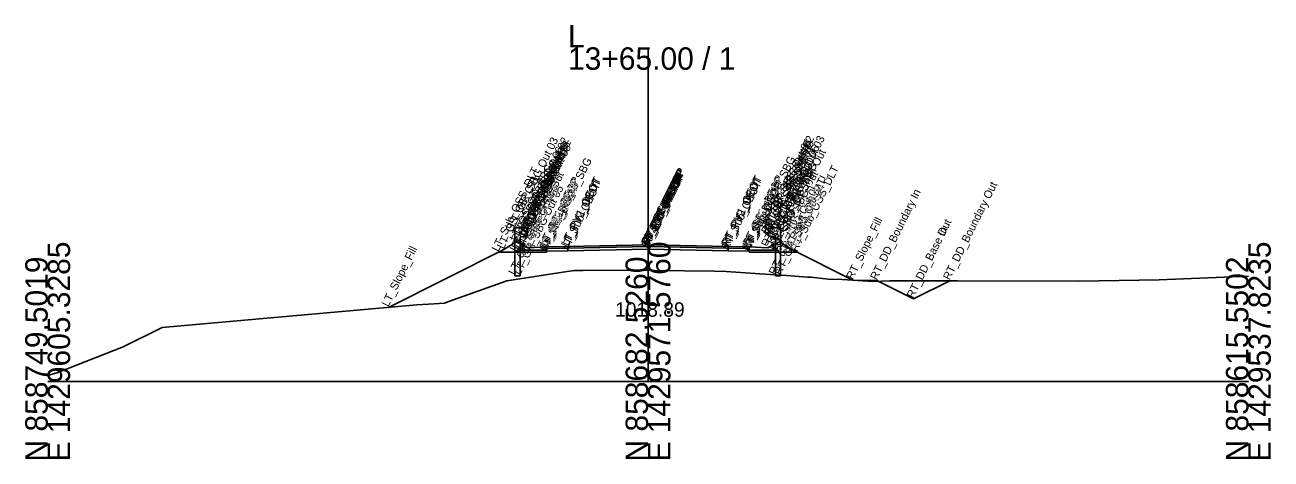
# Model space of a CAD drawing. Extents: x -26 to 2303, y -10 to 19558.
# Drawn here: x 1147.2 to 1302.8, y 11490.3 to 11544.5 of the extents above; entities that cross this region are included whole.
import ezdxf

# ---------------------------------------------------------------- set-up
doc = ezdxf.new("R2010")
doc.units = 0
for name, color, linetype in [('Default', 7, 'Continuous'), ('Exist Cross Section Cell', 7, 'Continuous'), ('Exist XS Center Line Elevation Label', 7, 'Continuous'), ('Exist XS Ground Line', 7, 'Continuous'), ('Prop CMT Conc Surface', 7, 'Continuous'), ('Prop CMT Concrete Structures', 7, 'Continuous'), ('Prop CMT Ditch DDE', 7, 'Continuous'), ('Prop CMT Guardrail SBG', 7, 'Continuous'), ('Prop CMT Pvmt Course 1', 7, 'Continuous'), ('Prop CMT Pvmt Course 2', 7, 'Continuous'), ('Prop CMT Pvmt Course SBG', 7, 'Continuous'), ('Prop CMT Pvmt Surface', 7, 'Continuous'), ('Prop CMT Pvmt Surface Shoulder', 7, 'Continuous'), ('Prop CMT Shld Paved Course 1', 7, 'Continuous'), ('Prop CMT Shld Paved Course 2', 7, 'Continuous'), ('Prop CMT Slope Grass', 7, 'Continuous'), ('Prop CMT Subgrade Earthwork', 7, 'Continuous'), ('Prop XS Dump Level', 7, 'Continuous')]:
    doc.layers.add(name, color=color, linetype=linetype)

msp = doc.modelspace()

# ---------------------------------------------------------------- linework, layer by layer
at = {"layer": 'Exist Cross Section Cell'}
for p, q in [((1225, 11500), (1225, 11541.74)), ((1150, 11500), (1225, 11500)), ((1225, 11500), (1300, 11500))]:
    msp.add_line(p, q, dxfattribs=at)
at = {"layer": 'Exist XS Ground Line'}
msp.add_lwpolyline([(1150, 11500.73), (1151.29, 11501.14), (1159.43, 11504.31), (1164.32, 11506.75), (1196.14, 11509.58), (1198.3, 11509.7), (1199.59, 11509.77), (1200.11, 11510), (1207.36, 11512.57), (1214.92, 11513.73), (1215.81, 11513.85), (1216.88, 11513.86), (1223.94, 11513.91), (1225, 11513.89), (1225.83, 11513.87), (1233.32, 11513.77), (1234.77, 11513.72), (1238.96, 11513.44), (1242.32, 11513.25), (1244.97, 11513.05), (1245.36, 11513.03), (1247.55, 11512.79), (1249.26, 11512.74), (1253.14, 11512.51), (1255.23, 11512.58), (1263.68, 11512.59), (1278.84, 11512.52), (1288.84, 11512.7), (1300, 11513.16)], dxfattribs=at)
at = {"layer": 'Prop CMT Conc Surface'}
for points in [[(1212.3, 11516.81), (1209.97, 11516.71), (1209.3, 11517.06)], [(1237.64, 11516.81), (1239.97, 11516.71), (1240.64, 11517.06)]]:
    msp.add_lwpolyline(points, dxfattribs=at)
at = {"layer": 'Prop CMT Concrete Structures'}
for points in [[(1212.3, 11516.81), (1209.97, 11516.71), (1209.3, 11517.06)], [(1209.3, 11517.06), (1209.3, 11516.39)], [(1209.3, 11516.39), (1212.3, 11516.39)], [(1212.3, 11516.39), (1212.3, 11516.81)], [(1237.64, 11516.81), (1239.97, 11516.71), (1240.64, 11517.06)], [(1237.64, 11516.39), (1237.64, 11516.81)], [(1240.64, 11516.39), (1237.64, 11516.39)], [(1240.64, 11517.06), (1240.64, 11516.39)]]:
    msp.add_lwpolyline(points, dxfattribs=at)
at = {"layer": 'Prop CMT Ditch DDE'}
for points in [[(1250.59, 11512.66), (1253.59, 11512.6), (1258.15, 11510.32)], [(1258.15, 11510.32), (1262.69, 11512.59)], [(1258.15, 11510.32), (1258.15, 11510.32)]]:
    msp.add_lwpolyline(points, dxfattribs=at)
at = {"layer": 'Prop CMT Guardrail SBG'}
for points in [[(1208.37, 11513.21), (1208.37, 11519.21)], [(1208.37, 11519.21), (1209.7, 11519.21), (1209.97, 11518.92)], [(1209.97, 11518.92), (1209.7, 11518.63)], [(1241.57, 11519.21), (1240.24, 11519.21), (1239.97, 11518.92)], [(1239.97, 11518.92), (1240.24, 11518.63)], [(1241.57, 11513.21), (1241.57, 11519.21)], [(1209.97, 11518.34), (1209.7, 11518.05), (1209.03, 11518.05)], [(1209.03, 11518.05), (1209.03, 11513.21)], [(1209.7, 11518.63), (1209.97, 11518.34)], [(1240.24, 11518.63), (1239.97, 11518.34)], [(1239.97, 11518.34), (1240.24, 11518.05), (1240.91, 11518.05)], [(1240.91, 11518.05), (1240.91, 11513.21)], [(1209.03, 11513.21), (1208.37, 11513.21)], [(1240.91, 11513.21), (1241.57, 11513.21)]]:
    msp.add_lwpolyline(points, dxfattribs=at)
at = {"layer": 'Prop CMT Pvmt Course 1'}
for points in [[(1225, 11517.06), (1215, 11516.86)], [(1215, 11516.86), (1215, 11516.65)], [(1215, 11516.65), (1225, 11516.85)], [(1225, 11516.85), (1225, 11517.06)], [(1225, 11517.06), (1235, 11516.86)], [(1225, 11516.85), (1225, 11517.06)], [(1235, 11516.65), (1225, 11516.85)], [(1235, 11516.86), (1235, 11516.65)]]:
    msp.add_lwpolyline(points, dxfattribs=at)
msp.add_lwpolyline([(1225, 11516.85), (1225, 11516.93), (1225, 11516.93), (1225, 11516.85)], close=True, dxfattribs=at)
msp.add_lwpolyline([(1225, 11516.85), (1225, 11516.93), (1225, 11516.93), (1225, 11516.85)], close=True, dxfattribs=at)
at = {"layer": 'Prop CMT Pvmt Course 2'}
for points in [[(1225, 11516.85), (1215, 11516.65)], [(1215, 11516.65), (1215, 11516.32)], [(1215, 11516.32), (1225, 11516.52)], [(1225, 11516.52), (1225, 11516.85)], [(1225, 11516.52), (1225, 11516.85)], [(1225, 11516.85), (1235, 11516.65)], [(1235, 11516.32), (1225, 11516.52)], [(1235, 11516.65), (1235, 11516.32)]]:
    msp.add_lwpolyline(points, dxfattribs=at)
at = {"layer": 'Prop CMT Pvmt Course SBG'}
for points in [[(1212.3, 11516.39), (1209.3, 11516.39), (1208.8, 11516.39), (1208.55, 11516.14)], [(1208.55, 11516.14), (1212.3, 11516.14)], [(1212.3, 11516.14), (1212.3, 11516.39)], [(1237.64, 11516.14), (1237.64, 11516.39)], [(1237.64, 11516.39), (1240.64, 11516.39), (1241.14, 11516.39), (1241.39, 11516.14)], [(1241.39, 11516.14), (1237.64, 11516.14)]]:
    msp.add_lwpolyline(points, dxfattribs=at)
at = {"layer": 'Prop CMT Pvmt Surface'}
for points in [[(1225, 11517.06), (1215, 11516.86)], [(1225, 11517.06), (1235, 11516.86)]]:
    msp.add_lwpolyline(points, dxfattribs=at)
at = {"layer": 'Prop CMT Pvmt Surface Shoulder'}
for points in [[(1215, 11516.86), (1212.3, 11516.81)], [(1235, 11516.86), (1237.64, 11516.81)]]:
    msp.add_lwpolyline(points, dxfattribs=at)
at = {"layer": 'Prop CMT Shld Paved Course 1'}
for points in [[(1215, 11516.86), (1212.3, 11516.81)], [(1212.3, 11516.81), (1212.3, 11516.6)], [(1212.3, 11516.6), (1215, 11516.65)], [(1215, 11516.65), (1215, 11516.86)], [(1235, 11516.86), (1237.64, 11516.81)], [(1235, 11516.65), (1235, 11516.86)], [(1237.64, 11516.6), (1235, 11516.65)], [(1237.64, 11516.81), (1237.64, 11516.6)]]:
    msp.add_lwpolyline(points, dxfattribs=at)
at = {"layer": 'Prop CMT Shld Paved Course 2'}
for points in [[(1215, 11516.65), (1212.3, 11516.6)], [(1212.3, 11516.6), (1212.3, 11516.39), (1212.3, 11516.26)], [(1212.3, 11516.26), (1215, 11516.32)], [(1215, 11516.32), (1215, 11516.65)], [(1235, 11516.65), (1237.64, 11516.6)], [(1235, 11516.32), (1235, 11516.65)], [(1237.64, 11516.26), (1235, 11516.32)], [(1237.64, 11516.6), (1237.64, 11516.39), (1237.64, 11516.26)]]:
    msp.add_lwpolyline(points, dxfattribs=at)
at = {"layer": 'Prop CMT Slope Grass'}
for points in [[(1209.3, 11517.06), (1208.53, 11517.45), (1206.97, 11516.47), (1192.56, 11509.26)], [(1240.64, 11517.06), (1241.41, 11517.45), (1242.97, 11516.47), (1250.59, 11512.66)]]:
    msp.add_lwpolyline(points, dxfattribs=at)
at = {"layer": 'Prop CMT Subgrade Earthwork'}
for points in [[(1212.3, 11516.14), (1208.55, 11516.14), (1206.3, 11516.14)], [(1215, 11516.32), (1212.3, 11516.26)], [(1212.3, 11516.26), (1212.3, 11516.14)], [(1225, 11516.52), (1215, 11516.32)], [(1225, 11516.52), (1235, 11516.32)], [(1235, 11516.32), (1237.64, 11516.26)], [(1237.64, 11516.26), (1237.64, 11516.14)], [(1237.64, 11516.14), (1241.39, 11516.14), (1243.64, 11516.14)]]:
    msp.add_lwpolyline(points, dxfattribs=at)

# ---------------------------------------------------------------- texts
at = {"layer": 'Default'}
msp.add_text('-', height=0.0001, dxfattribs=at).set_placement((1150, 11500))
at = {"layer": 'Exist Cross Section Cell'}
for s, p in [('L', (1215, 11541.74)), ('13+65.00 / 1', (1215, 11538.94))]:
    msp.add_text(s, height=2.8, dxfattribs=at).set_placement(p)
for s, p in [('E 1429605.3285', (1152.8, 11490)), ('E 1429571.5760', (1227.8, 11490)), ('E 1429537.8235', (1302.8, 11490)), ('N 858749.5019', (1150, 11490)), ('N 858682.5260', (1225, 11490)), ('N 858615.5502', (1300, 11490))]:
    msp.add_text(s, height=2.8, rotation=90, dxfattribs=at).set_placement(p)
at = {"layer": 'Exist XS Center Line Elevation Label'}
msp.add_text('1018.89', height=1.8, dxfattribs=at).set_placement((1220.88, 11508.09))
at = {"layer": 'Prop XS Dump Level'}
for s, p in [('LT_GR_SBG Out 03', (1208.37, 11519.21)), ('LT_GR_SBG Out 02', (1209.7, 11519.21)), ('LT_GR_SBG Out 09', (1209.7, 11518.63)), ('LT_GR_SBG Out 01', (1209.97, 11518.92)), ('RT_GR_SBG Out 01', (1239.97, 11518.92)), ('RT_GR_SBG Out 08', (1239.97, 11518.34)), ('RT_GR_SBG Out 02', (1240.24, 11519.21)), ('RT_GR_SBG Out 09', (1240.24, 11518.63)), ('RT_GR_SBG Out 03', (1241.57, 11519.21)), ('LT_SBG_C1 Shelf Out', (1208.8, 11516.39)), ('LT_GR_SBG Out 06', (1209.03, 11518.05)), ('LT_GR_SBG Out 07', (1209.7, 11518.05)), ('LT_GR_SBG Out 08', (1209.97, 11518.34)), ('RT_GR_SBG Out 07', (1240.24, 11518.05)), ('RT_GR_SBG Out 06', (1240.91, 11518.05)), ('RT_SBG_C1 Shelf Out', (1241.14, 11516.39)), ('LT_Sub_OSS_DLT', (1206.3, 11516.14)), ('LT_GS_OS_SBG', (1208.53, 11517.45)), ('LT_CG_Top_BOC', (1209.3, 11517.06)), ('LT_Sub_OEOP_SBG', (1212.3, 11516.14)), ('RT_PV1_OEEOP', (1225, 11516.93)), ('RT_Sub_OEOP_SBG', (1237.64, 11516.14)), ('RT_CG_Top_BOC', (1240.64, 11517.06)), ('RT_GS_OS_SBG', (1241.41, 11517.45)), ('RT_Sub_OSS_DLT', (1243.64, 11516.14)), ('LT_GS_OS_CTL', (1206.97, 11516.47)), ('LT_Sub_SBG Out', (1208.55, 11516.14)), ('LT_CG_Bot_BOC', (1209.3, 11516.39)), ('LT_CG_Top_Gut', (1209.97, 11516.71)), ('LT_PS1_OEOP', (1212.3, 11516.81)), ('LT_PS2_OEOP', (1212.3, 11516.6)), ('LT_PV1_OEOT', (1215, 11516.86)), ('LT_PV2_OEOT', (1215, 11516.65)), ('RT_PV2_OEEOP', (1225, 11516.85)), ('LT_PV1_OEEOP', (1225, 11516.93)), ('LT_PV2_OEEOP', (1225, 11516.85)), ('RT_Sub_OEEOP', (1225, 11516.52)), ('RT_PV1_IEEOP', (1225, 11516.93)), ('RT_PV2_IEEOP', (1225, 11516.85)), ('LT_Sub_OEEOP', (1225, 11516.52)), ('LT_PV1_IEEOP', (1225, 11516.93)), ('LT_PV2_IEEOP', (1225, 11516.85)), ('RT_PV1_OEOT', (1235, 11516.86)), ('RT_PV2_OEOT', (1235, 11516.65)), ('RT_Sub_OEOT', (1235, 11516.32)), ('RT_PS1_OEOP', (1237.64, 11516.81)), ('RT_PS2_OEOP', (1237.64, 11516.6)), ('RT_CG_Top_Gut', (1239.97, 11516.71)), ('RT_CG_Bot_BOC', (1240.64, 11516.39)), ('RT_Sub_SBG Out', (1241.39, 11516.14)), ('RT_GS_OS_CTL', (1242.97, 11516.47)), ('LT_GR_SBG Out 04', (1208.37, 11513.21)), ('LT_GR_SBG Out 05', (1209.03, 11513.21)), ('LT_Sub_OEOP', (1212.3, 11516.26)), ('LT_CG_Bot_IE', (1212.3, 11516.39)), ('LT_Sub_OEOT', (1215, 11516.32)), ('RT_Sub_OEOP', (1237.64, 11516.26)), ('RT_CG_Bot_IE', (1237.64, 11516.39)), ('RT_GR_SBG Out 05', (1240.91, 11513.21)), ('RT_GR_SBG Out 04', (1241.57, 11513.21)), ('RT_DD_Boundary In', (1253.59, 11512.6)), ('RT_DD_Boundary Out', (1262.69, 11512.59)), ('PV1_PGL', (1225, 11517.06)), ('PV2_PGL', (1225, 11516.85)), ('RT_Slope_Fill', (1250.59, 11512.66)), ('RT_DD_Base Out', (1258.15, 11510.32)), ('RT_DD_Base In', (1258.15, 11510.32)), ('LT_Slope_Fill', (1192.56, 11509.26))]:
    msp.add_text(s, height=1, rotation=63.5833, dxfattribs=at).set_placement(p)

doc.saveas('drawing.dxf')
